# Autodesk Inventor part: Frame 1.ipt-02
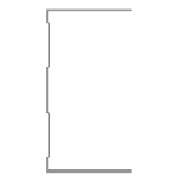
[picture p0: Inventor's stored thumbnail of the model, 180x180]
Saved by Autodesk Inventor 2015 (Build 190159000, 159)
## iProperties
IsCustomPart: 1
Created: 2015-04
Part Number: Frame 1.ipt-02
Material: Aluminum 6061
Description: Kévin Novo
Document SubType Name: Modeling
Standard: Kevin
Designer: suporte
Standards Organization: Kevin
Language: en-US
Size Designation: (Unnamed 2)
Categories: <MemberInstance><Categories><Category DisplayName="Structural Shapes" InternalName="089c4875-fa83-4c05-b084-43b9cc11f5ed" Mnemonic="GRDR"><CategoryParameter Dis
Density: 2.7 g/cm^3
Appearance: Aluminum - Flat
_CCFamilyMember: 2
_CCFamilyDisplayName: Kévin - Kévin Novo
_FrameMemberDoc: Frame Member File
_Version: 15.0.0
_GetPNFromCC: 1
G_W: 50,000 mm
G_H: 75,000 mm
G_L: 2100,000 mm
+B6702A2A-2177-46D1-A6FB-406ACC042074+CUTDETAIL1: Notch
Author: suporte
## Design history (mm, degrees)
node "Start Plane"
node "End Plane"
sketch "Sketch"
  geometry: L1 (24.7, 37.5)-(24.7, 36.9); L2 (24.7, 36.9)-(-24.7, 36.9); L3 (-24.7, -36.9)-(24.7, -36.9); L4 (24.7, -36.9)-(24.7, -37.5); L5 (24.7, -37.5)-(-25.3, -37.5); L6 (-25.3, 37.5)-(24.7, 37.5); L7 (-24.7, 36.9)-(-24.7, 31.9); L8 (-24.7, 31.9)-(-23.3, 30.5); L9 (-23.3, 30.5)-(-23.3, 10.934); L10 (-23.3, 10.934)-(-24.7, 9.534); L11 (-24.7, 9.534)-(-24.7, -9.534); L12 (-24.7, -9.534)-(-23.3, -10.934); L13 (-23.3, -10.934)-(-23.3, -30.5); L14 (-23.3, -30.5)-(-24.7, -31.9); L15 (-24.7, -31.9)-(-24.7, -36.9); L16 (-25.3, -37.5)-(-25.3, -31.651); L17 (-25.3, -31.651)-(-23.9, -30.251); L18 (-23.9, -30.251)-(-23.9, -11.183); L19 (-23.9, -11.183)-(-25.3, -9.783); L20 (-25.3, -9.783)-(-25.3, 9.783); L21 (-25.3, 9.783)-(-23.9, 11.183); L22 (-23.9, 11.183)-(-23.9, 30.251); L23 (-23.9, 30.251)-(-25.3, 31.651); L24 (-25.3, 31.651)-(-25.3, 37.5); L25 (-25.3, 0)-(30.37, 0); 3 further points
  constraints: 50 end point, 10 point on line, 9 parallel, 5 perpendicular, 4 equal length, 3 midpoint, 3 vertical, 2 vertical alignment, 1 collinear, 1 horizontal, 1 horizontal alignment
  dimensions: "d3" = 0.6 distance of L1.start L1.end (= d6); "d5" = 75 distance between parallel lines of L5 L6; "d6" = 0.6 distance between parallel lines of L24 L7 (= d8); "d7" = 0.6 distance between parallel lines of L8 L23 (= d8); "d8" = 0.6 distance between parallel lines of L22 L9 (= d12); "Espessura" = 0.6 distance between parallel lines of L17 L14; "d10" = 0.6 distance between parallel lines of L13 L18 (= Espessura); "d11" = 0.6 distance between parallel lines of L12 L19 (= Espessura); "d12" = 0.6 distance between parallel lines of L21 L10 (= d11); "d13" = 5 distance of L2.end L7.end; "d15" = 135 deg angle of L9 L8; "d16" = 2 distance between parallel lines of L24 L9; "d17" = 50 distance of L6.start L1.start
extrude "Body" join sketch "Sketch" stored distance "d24" = 0.13; taper "d25" = 0 deg
node "Driven Length"
  sketch "Sketch10"
    geometry: L1 (0, 0)-(10, 0) reference
    constraints: 2 end point, 1 horizontal
  workplane "Work Plane7"
  sketch "Sketch11"
    geometry: L1 (-2, 0)-(12, 0) reference; L2 (-2, 2100)-(12, 2100) reference
    dimensions: "d27" = 2100 distance between parallel lines of L1 L2 (derived)
workplane "Work Plane8"
workplane "Work Plane9"
workplane "Work Plane10"
sketch "Sketch12"
  geometry: L1 (24.7, 37.5)-(24.7, 36.9); L2 (24.7, 36.9)-(-24.7, 36.9); L3 (-24.7, 36.9)-(-24.7, 31.9); L4 (-24.7, 31.9)-(-23.3, 30.5); L5 (-23.3, 30.5)-(-23.3, 10.934); L6 (-23.3, 10.934)-(-24.7, 9.534); L7 (-24.7, 9.534)-(-24.7, -9.534); L8 (-24.7, -9.534)-(-23.3, -10.934); L9 (-23.3, -10.934)-(-23.3, -30.5); L10 (-23.3, -30.5)-(-24.7, -31.9); L11 (-24.7, -31.9)-(-24.7, -36.9); L12 (-24.7, -36.9)-(24.7, -36.9); L13 (24.7, -36.9)-(24.7, -37.5); L14 (24.7, -37.5)-(-25.3, -37.5); L15 (-25.3, -37.5)-(-25.3, -31.651); L16 (-25.3, -31.651)-(-23.9, -30.251); L17 (-23.9, -30.251)-(-23.9, -11.183); L18 (-23.9, -11.183)-(-25.3, -9.783); L19 (-25.3, -9.783)-(-25.3, 9.783); L20 (-25.3, 9.783)-(-23.9, 11.183); L21 (-23.9, 11.183)-(-23.9, 30.251); L22 (-23.9, 30.251)-(-25.3, 31.651); L23 (-25.3, 31.651)-(-25.3, 37.5); L24 (-25.3, 37.5)-(24.7, 37.5)
  constraints: 48 end point, 10 point on line
extrude "Extrusion3" cut sketch "Sketch12" stored distance "d36" = 0.13; taper "d37" = 0 deg
body "Solid1"
other parameters: "G_OFFSET_START" = 0 [user parameter; used in 1 equation term], "G_OFFSET_END" = 0 [user parameter; used in 1 equation term], "d22" = 0 (computed from G_OFFSET_START), "G_L" = 2100 (= d27) [user parameter], "d34" = 90 deg
